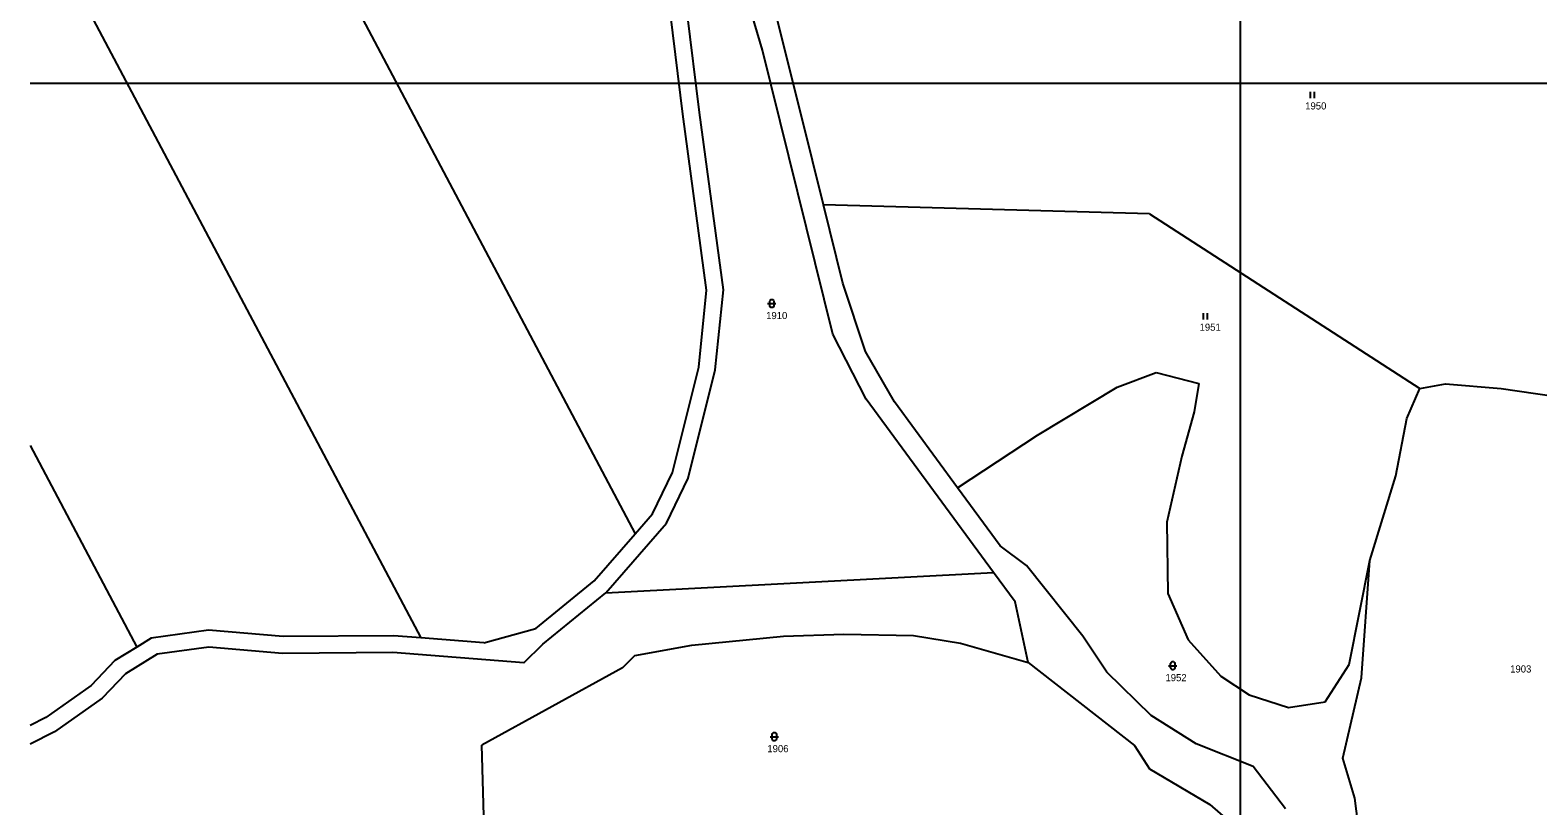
# Model space of a CAD drawing. Extents: x -801853 to -800578, y -1017479 to -1016338.
# Drawn here: x -801848 to -801488.1, y -1017172.4 to -1016987.3 of the extents above; entities that cross this region are included whole.
import ezdxf

# ---------------------------------------------------------------- set-up
doc = ezdxf.new("R2010")
doc.units = 0
for name, color, linetype in [('Default', 7, 'Continuous'), ('KLADY_ZMVM', 7, 'Continuous'), ('KN_HRANICE', 7, 'Continuous'), ('KN_KULTURY', 7, 'Continuous'), ('KN_PARCELY', 7, 'Continuous'), ('LEGENDA', 7, 'Continuous')]:
    doc.layers.add(name, color=color, linetype=linetype)

# ---------------------------------------------------------------- blocks, each defined once
blk = doc.blocks.new('306')
at = {"layer": 'Default'}
for p, q in [((-0.5, 1.5), (-0.5, 0)), ((0.5, 0), (0.5, 1.5))]:
    blk.add_line(p, q, dxfattribs=at)
blk = doc.blocks.new('316')
at = {"layer": 'Default'}
for points in [[(-1, 1), (0.27, 1), (1, 1)], [(-0.5, 1.5), (-0.4, 1.79), (-0.15, 1.97), (0.16, 1.97), (0.41, 1.79), (0.51, 1.5), (0.51, 0.5), (0.41, 0.21), (0.16, 0.03), (-0.15, 0.03), (-0.4, 0.21), (-0.5, 0.5), (-0.5, 1.5)]]:
    blk.add_lwpolyline(points, dxfattribs=at)

msp = doc.modelspace()

# ---------------------------------------------------------------- linework, layer by layer
at = {"layer": 'KLADY_ZMVM'}
msp.add_line((-801848.02, -1017000), (-800625, -1017000), dxfattribs=at)
at = {"layer": 'KN_HRANICE'}
for p, q in [((-801784.27, -1016955.14), (-801703.59, -1017107.44)), ((-801661.3, -1017018.39), (-801676.44, -1016957.72)), ((-801673.18, -1016992.05), (-801681.07, -1016965.55)), ((-801835.76, -1016979.41), (-801754.78, -1017132.31)), ((-801688.27, -1017006.93), (-801691.2, -1016983.13)), ((-801692.25, -1017007.35), (-801695.19, -1016983.45)), ((-801656.4, -1017059.84), (-801673.18, -1016992.05)), ((-801686.56, -1017049.34), (-801692.25, -1017007.35)), ((-801682.53, -1017049.27), (-801688.27, -1017006.93)), ((-801658.68, -1017029.01), (-801661.3, -1017018.39)), ((-801580.84, -1017031.1), (-801658.68, -1017029.01)), ((-801654.06, -1017047.7), (-801658.68, -1017029.01)), ((-801580.84, -1017031.1), (-801516.27, -1017072.8)), ((-801648.61, -1017063.96), (-801654.06, -1017047.7)), ((-801688.42, -1017067.67), (-801686.56, -1017049.34)), ((-801684.47, -1017068.36), (-801682.53, -1017049.27)), ((-801648.47, -1017075.34), (-801656.4, -1017059.84)), ((-801641.69, -1017076), (-801648.61, -1017063.96)), ((-801694.71, -1017092.82), (-801688.42, -1017067.67)), ((-801690.93, -1017094.18), (-801684.47, -1017068.36)), ((-801588.56, -1017072.48), (-801579.21, -1017069.02)), ((-801579.21, -1017069.02), (-801569.05, -1017071.63)), ((-801607.54, -1017083.93), (-801588.56, -1017072.48)), ((-801569.05, -1017071.63), (-801570.19, -1017078.34)), ((-801519.39, -1017079.95), (-801516.27, -1017072.8)), ((-801516.27, -1017072.8), (-801510.16, -1017071.7)), ((-801510.16, -1017071.7), (-801496.87, -1017072.82)), ((-801496.87, -1017072.82), (-801478.06, -1017075.54)), ((-801618.05, -1017116.71), (-801648.47, -1017075.34)), ((-801626.64, -1017096.51), (-801641.69, -1017076)), ((-801570.19, -1017078.34), (-801573.12, -1017088.9)), ((-801522.03, -1017093.64), (-801519.39, -1017079.95)), ((-801626.64, -1017096.51), (-801607.54, -1017083.93)), ((-801848.02, -1017086.43), (-801822.56, -1017134.47)), ((-801573.12, -1017088.9), (-801576.66, -1017104.66)), ((-801699.48, -1017102.72), (-801694.71, -1017092.82)), ((-801696.11, -1017104.95), (-801690.93, -1017094.18)), ((-801528.21, -1017113.81), (-801522.03, -1017093.64)), ((-801616.44, -1017110.33), (-801626.64, -1017096.51)), ((-801710.59, -1017121.54), (-801696.11, -1017104.95)), ((-801703.59, -1017107.44), (-801699.48, -1017102.72)), ((-801576.66, -1017104.66), (-801576.49, -1017121.72)), ((-801713.38, -1017118.65), (-801703.59, -1017107.44)), ((-801610.15, -1017115.02), (-801616.44, -1017110.33)), ((-801596.71, -1017131.88), (-801610.15, -1017115.02)), ((-801533.13, -1017138.67), (-801528.21, -1017113.81)), ((-801530.19, -1017141.81), (-801528.21, -1017113.81)), ((-801727.32, -1017130.01), (-801713.38, -1017118.65)), ((-801710.59, -1017121.54), (-801618.05, -1017116.71)), ((-801612.93, -1017123.67), (-801618.05, -1017116.71)), ((-801725.64, -1017133.8), (-801710.59, -1017121.54)), ((-801609.81, -1017138.16), (-801612.93, -1017123.67)), ((-801576.49, -1017121.72), (-801571.59, -1017132.79)), ((-801805.47, -1017130.48), (-801819.1, -1017132.33)), ((-801787.61, -1017131.99), (-801805.47, -1017130.48)), ((-801739.74, -1017133.5), (-801727.32, -1017130.01)), ((-801822.56, -1017134.47), (-801827.78, -1017137.72)), ((-801819.1, -1017132.33), (-801822.56, -1017134.47)), ((-801805.37, -1017134.5), (-801817.72, -1017136.18)), ((-801787.76, -1017135.99), (-801805.37, -1017134.5)), ((-801761.28, -1017131.8), (-801787.61, -1017131.99)), ((-801754.78, -1017132.31), (-801761.28, -1017131.8)), ((-801739.74, -1017133.5), (-801754.78, -1017132.31)), ((-801730.18, -1017138.26), (-801725.64, -1017133.8)), ((-801703.69, -1017136.49), (-801690.07, -1017134.01)), ((-801690.07, -1017134.01), (-801668.19, -1017131.9)), ((-801668.19, -1017131.9), (-801653.81, -1017131.39)), ((-801653.81, -1017131.39), (-801637.15, -1017131.68)), ((-801637.15, -1017131.68), (-801625.98, -1017133.55)), ((-801625.98, -1017133.55), (-801609.81, -1017138.16)), ((-801591.03, -1017140.5), (-801596.71, -1017131.88)), ((-801571.59, -1017132.79), (-801563.8, -1017141.41)), ((-801827.78, -1017137.72), (-801833.47, -1017143.63)), ((-801817.72, -1017136.18), (-801825.24, -1017140.85)), ((-801761.42, -1017135.8), (-801787.76, -1017135.99)), ((-801730.18, -1017138.26), (-801761.42, -1017135.8)), ((-801703.69, -1017136.49), (-801706.64, -1017139.46)), ((-801609.81, -1017138.16), (-801584.39, -1017157.99)), ((-801825.24, -1017140.85), (-801830.85, -1017146.68)), ((-801706.64, -1017139.46), (-801740.19, -1017157.87)), ((-801580.41, -1017150.78), (-801591.03, -1017140.5)), ((-801563.8, -1017141.41), (-801557.02, -1017145.9)), ((-801538.88, -1017147.55), (-801533.13, -1017138.67)), ((-801833.47, -1017143.63), (-801844.25, -1017151.25)), ((-801534.71, -1017160.98), (-801530.19, -1017141.81)), ((-801830.85, -1017146.68), (-801842.17, -1017154.68)), ((-801557.02, -1017145.9), (-801547.68, -1017148.92)), ((-801547.68, -1017148.92), (-801538.88, -1017147.55)), ((-801844.25, -1017151.25), (-801848.02, -1017153.16)), ((-801569.67, -1017157.56), (-801580.41, -1017150.78)), ((-801842.17, -1017154.68), (-801848.02, -1017157.64)), ((-801739.66, -1017177.55), (-801740.19, -1017157.87)), ((-801584.39, -1017157.99), (-801580.79, -1017163.54)), ((-801556.12, -1017162.99), (-801569.67, -1017157.56)), ((-801548.37, -1017173.06), (-801556.12, -1017162.99)), ((-801531.84, -1017170.53), (-801534.71, -1017160.98)), ((-801580.79, -1017163.54), (-801566.4, -1017172.05)), ((-801530.73, -1017179.18), (-801531.84, -1017170.53)), ((-801566.4, -1017172.05), (-801552.14, -1017184.41))]:
    msp.add_line(p, q, dxfattribs=at)
at = {"layer": 'LEGENDA'}
msp.add_lwpolyline([(-801559.16, -1017339.08), (-800718.16, -1017339.08), (-800718.16, -1016745.08), (-801559.16, -1016745.08)], close=True, dxfattribs=at)

# ---------------------------------------------------------------- block references
at = {"layer": 'KN_KULTURY'}
for name, p in [('306', (-801541.96, -1017003.54)), ('316', (-801670.99, -1017053.54)), ('306', (-801567.5, -1017056.32)), ('316', (-801575.28, -1017139.92)), ('316', (-801670.39, -1017156.86))]:
    msp.add_blockref(name, p, dxfattribs=at)

# ---------------------------------------------------------------- texts
at = {"layer": 'KN_PARCELY'}
for s, p in [('1950', (-801543.66, -1017006.24)), ('1910', (-801672.34, -1017056.24)), ('1951', (-801568.87, -1017059.02)), ('1952', (-801577.02, -1017142.62)), ('1903', (-801494.74, -1017140.55)), ('1906', (-801672.05, -1017159.56))]:
    msp.add_text(s, height=1.7, dxfattribs=at).set_placement(p)

doc.saveas('drawing.dxf')
